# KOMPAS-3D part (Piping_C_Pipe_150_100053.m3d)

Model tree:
1. Plane XY
2. Plane ZX
3. Plane ZY
4. X Axis
5. Y Axis
6. Z Axis
7. Origin
8. Path  (labels: Отвод 90 Dy 150; Труба Dy 150)
9. Plane of section
10. Section of pipe
11. Pipe
     Толщина стенки 1 = 1

Referenced files in C:\Program Files\ASCON\KOMPAS-3D V10\Libs\Piping\Models\Tanks\: Tanks.a3d
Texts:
  Pipe Dn 150
  Steel ASTM A295
  Three Point Plane
  Plane at Angle
  Line and Point Plane
  Axis through Two Vertices
  Axis of Feature
  Axis of Conical Surface
  Axis through Edge
  Приклеить элемент выдавливания
  Приклеить элемент вращения
  Приклеить кинематический элемент
  Приклеить элемент по сечениям
  Trim by Surface
  Trim by Sketch
  Feature with No History
  Intersection Axis of Two Planes
  Two Line Plane
  Line and Face Plane
  Bend by line
  Hole in sheet body
  Cut in sheet body
  Point in CM
  Linear Dimension from Line to Point
  Surface Finish Symbol
  Geometric Tolerance Symbol
  Текст на чертеже
  Линия-выноска #1
  Линия-выноска #2
  Линия-выноска #3
  Отклонения формы и база
  Марка координационной оси
  Марка/позиционное обозначение с линией-выноской
  Марка/позиционное обозначение на линии
  Марка/позиционное обозначение без линии-выноски
  Отвод 90 Dy 150
  Труба Dy 150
